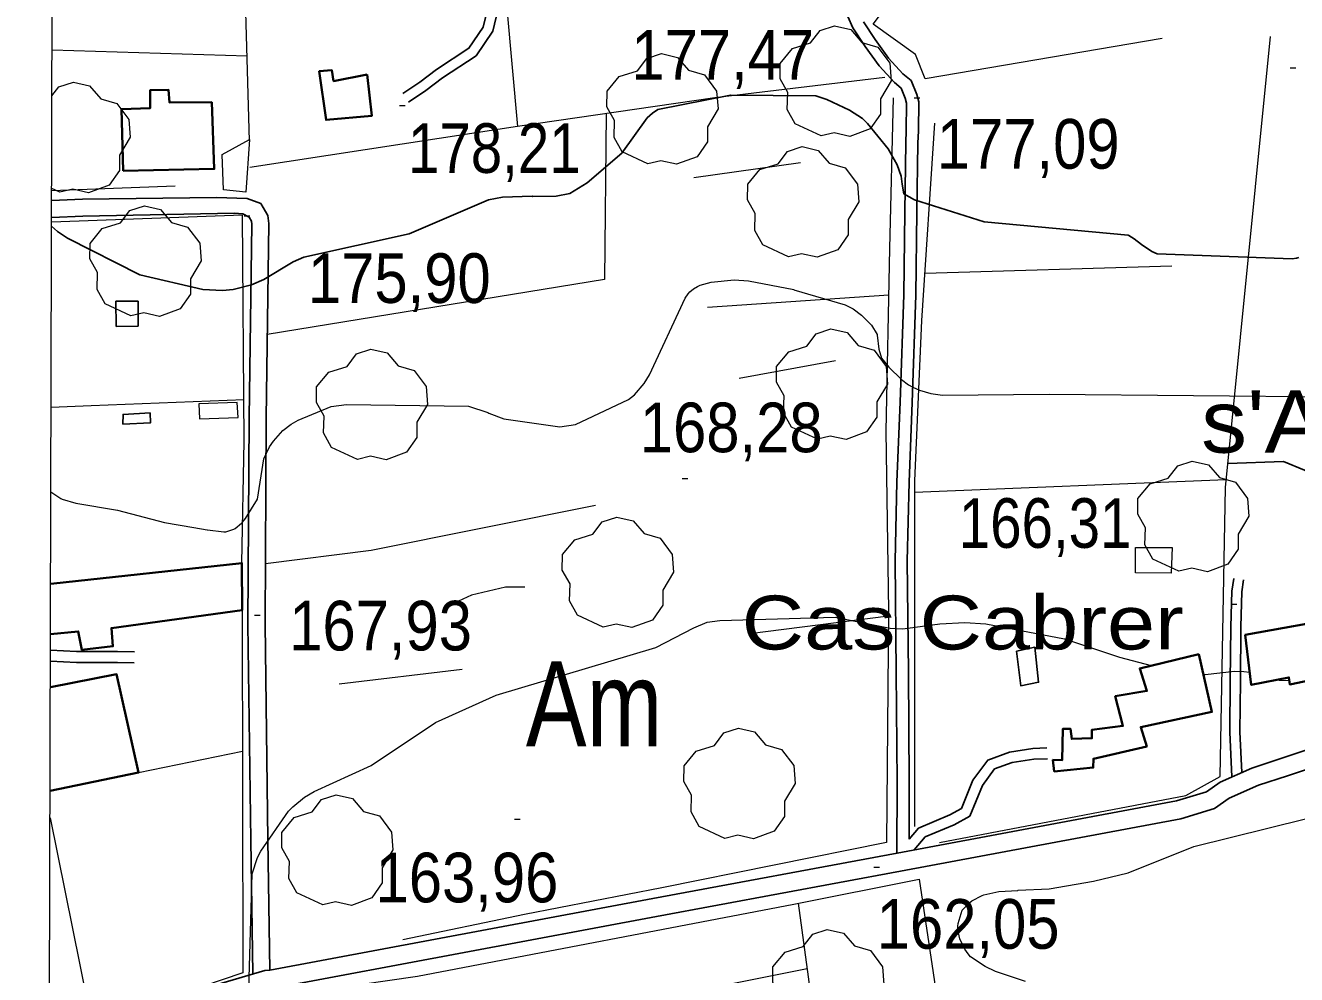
# Model space of a CAD drawing. Extents: x 480269 to 484877, y 4383588 to 4386804.
# Drawn here: x 480523.1 to 480747.1, y 4385794.6 to 4385961.9 of the extents above; entities that cross this region are included whole.
import ezdxf
from ezdxf.enums import TextEntityAlignment as Align

# ---------------------------------------------------------------- set-up
doc = ezdxf.new("R2010")
doc.units = 0
doc.header["$LTSCALE"] = 3.8
doc.linetypes.add('LONG_DASHED', pattern=[7.5, 6, -1.5])
doc.linetypes.add('MEDIUM_DASHED', pattern=[4.5, 3, -1.5])
for name, color, linetype, lineweight in [('1', 7, 'Continuous', 13), ('21', 7, 'Continuous', 25), ('25', 7, 'LONG_DASHED', 25), ('29', 7, 'Continuous', 13), ('36', 7, 'Continuous', 25), ('38', 7, 'Continuous', 25), ('47', 7, 'Continuous', 35), ('48', 7, 'MEDIUM_DASHED', 25), ('51', 7, 'Continuous', 13), ('7', 7, 'Continuous', 13), ('8', 7, 'Continuous', 25), ('9', 7, 'Continuous', 13)]:
    doc.layers.add(name, color=color, linetype=linetype, lineweight=lineweight)
doc.layers.add('31', color=7, linetype='Continuous')
doc.layers.add('5', color=7, linetype='Continuous')

msp = doc.modelspace()

# ---------------------------------------------------------------- linework, layer by layer
at = {"layer": '1'}
msp.add_lwpolyline([(480529.1, 4386456.6), (484105.5, 4386448.1), (484100.5, 4384135.8), (480523.1, 4384144.4)], close=True, dxfattribs=at)
at = {"layer": '21'}
for points in [[(480540.25, 4385891.65), (480545.16, 4385891.9), (480545.07, 4385893.64), (480540.32, 4385893.36)], [(480700.95, 4385852.32), (480701.64, 4385846.17), (480698.49, 4385845.55), (480697.75, 4385851.63)]]:
    msp.add_lwpolyline(points, close=True, dxfattribs=at)
at = {"layer": '25'}
msp.add_lwpolyline([(480767.61, 4385841.45), (480767.42, 4385847.58), (480771.36, 4385854.49), (480775.03, 4385857.97), (480782.21, 4385867), (480780.15, 4385876.58), (480770.59, 4385882.49), (480763.05, 4385883.56), (480753.17, 4385881.59), (480744.81, 4385885.08), (480735, 4385884.7)], dxfattribs=at)
at = {"layer": '29'}
msp.add_line((480529.17, 4385932.52), (480527.74, 4385933.19), dxfattribs=at)
for points in [[(480663.3, 4385942.45), (480658.76, 4385944.57), (480657.35, 4385947.11), (480657.45, 4385950.09), (480656.08, 4385952.5), (480656.12, 4385955.25), (480658.28, 4385957.85), (480661.47, 4385958.85), (480663.12, 4385961.04), (480665.69, 4385961.87), (480668.55, 4385961.22), (480670.5, 4385958.95), (480673.31, 4385958.13), (480675.44, 4385955.28), (480675.68, 4385952.15), (480673.8, 4385949), (480673.8, 4385946.32), (480671.98, 4385943.71), (480668.36, 4385942.37), (480665.59, 4385943)], [(480632.77, 4385937.54), (480628.23, 4385939.66), (480626.82, 4385942.2), (480626.92, 4385945.18), (480625.55, 4385947.59), (480625.59, 4385950.34), (480627.75, 4385952.94), (480630.94, 4385953.94), (480632.59, 4385956.13), (480635.16, 4385956.96), (480638.02, 4385956.31), (480639.97, 4385954.04), (480642.78, 4385953.22), (480644.91, 4385950.37), (480645.15, 4385947.24), (480643.27, 4385944.09), (480643.27, 4385941.41), (480641.45, 4385938.8), (480637.83, 4385937.46), (480635.06, 4385938.09)], [(480657.56, 4385921.15), (480653.02, 4385923.27), (480651.61, 4385925.81), (480651.71, 4385928.79), (480650.34, 4385931.2), (480650.38, 4385933.95), (480652.54, 4385936.55), (480655.73, 4385937.55), (480657.38, 4385939.74), (480659.95, 4385940.57), (480662.81, 4385939.92), (480664.76, 4385937.65), (480667.57, 4385936.83), (480669.7, 4385933.98), (480669.94, 4385930.85), (480668.06, 4385927.7), (480668.06, 4385925.02), (480666.24, 4385922.41), (480662.62, 4385921.07), (480659.85, 4385921.7)], [(480541.67, 4385910.72), (480537.13, 4385912.84), (480535.72, 4385915.38), (480535.82, 4385918.36), (480534.45, 4385920.77), (480534.49, 4385923.52), (480536.65, 4385926.12), (480539.84, 4385927.12), (480541.49, 4385929.31), (480544.06, 4385930.14), (480546.92, 4385929.49), (480548.87, 4385927.22), (480551.68, 4385926.4), (480553.81, 4385923.55), (480554.05, 4385920.42), (480552.17, 4385917.27), (480552.17, 4385914.59), (480550.35, 4385911.98), (480546.73, 4385910.64), (480543.96, 4385911.27)], [(480662.65, 4385889.01), (480658.11, 4385891.13), (480656.7, 4385893.67), (480656.8, 4385896.65), (480655.43, 4385899.06), (480655.47, 4385901.81), (480657.63, 4385904.41), (480660.82, 4385905.41), (480662.47, 4385907.6), (480665.04, 4385908.43), (480667.9, 4385907.78), (480669.85, 4385905.51), (480672.66, 4385904.69), (480674.79, 4385901.84), (480675.03, 4385898.71), (480673.15, 4385895.56), (480673.15, 4385892.88), (480671.33, 4385890.27), (480667.71, 4385888.93), (480664.94, 4385889.56)], [(480581.6, 4385885.44), (480577.06, 4385887.56), (480575.65, 4385890.1), (480575.75, 4385893.08), (480574.38, 4385895.49), (480574.42, 4385898.24), (480576.58, 4385900.84), (480579.77, 4385901.84), (480581.42, 4385904.03), (480583.99, 4385904.86), (480586.85, 4385904.21), (480588.8, 4385901.94), (480591.61, 4385901.12), (480593.74, 4385898.27), (480593.98, 4385895.14), (480592.1, 4385891.99), (480592.1, 4385889.31), (480590.28, 4385886.7), (480586.66, 4385885.36), (480583.89, 4385885.99)], [(480726.33, 4385865.72), (480721.79, 4385867.84), (480720.38, 4385870.38), (480720.48, 4385873.36), (480719.11, 4385875.77), (480719.15, 4385878.52), (480721.31, 4385881.12), (480724.5, 4385882.12), (480726.15, 4385884.31), (480728.72, 4385885.14), (480731.58, 4385884.49), (480733.53, 4385882.22), (480736.34, 4385881.4), (480738.47, 4385878.55), (480738.71, 4385875.42), (480736.83, 4385872.27), (480736.83, 4385869.59), (480735.01, 4385866.98), (480731.39, 4385865.64), (480728.62, 4385866.27)], [(480624.93, 4385855.86), (480620.39, 4385857.98), (480618.98, 4385860.52), (480619.08, 4385863.5), (480617.71, 4385865.91), (480617.75, 4385868.66), (480619.91, 4385871.26), (480623.1, 4385872.26), (480624.75, 4385874.45), (480627.32, 4385875.28), (480630.18, 4385874.63), (480632.13, 4385872.36), (480634.94, 4385871.54), (480637.07, 4385868.69), (480637.31, 4385865.56), (480635.43, 4385862.41), (480635.43, 4385859.73), (480633.61, 4385857.12), (480629.99, 4385855.78), (480627.22, 4385856.41)], [(480646.34, 4385818.63), (480641.8, 4385820.75), (480640.39, 4385823.29), (480640.49, 4385826.27), (480639.12, 4385828.68), (480639.16, 4385831.43), (480641.32, 4385834.03), (480644.51, 4385835.03), (480646.16, 4385837.22), (480648.73, 4385838.05), (480651.59, 4385837.4), (480653.54, 4385835.13), (480656.35, 4385834.31), (480658.48, 4385831.46), (480658.72, 4385828.33), (480656.84, 4385825.18), (480656.84, 4385822.5), (480655.02, 4385819.89), (480651.4, 4385818.55), (480648.63, 4385819.18)], [(480575.48, 4385806.9), (480570.94, 4385809.02), (480569.53, 4385811.56), (480569.63, 4385814.54), (480568.26, 4385816.95), (480568.3, 4385819.7), (480570.46, 4385822.3), (480573.65, 4385823.3), (480575.3, 4385825.49), (480577.87, 4385826.32), (480580.73, 4385825.67), (480582.68, 4385823.4), (480585.49, 4385822.58), (480587.62, 4385819.73), (480587.86, 4385816.6), (480585.98, 4385813.45), (480585.98, 4385810.77), (480584.16, 4385808.16), (480580.54, 4385806.82), (480577.77, 4385807.45)], [(480662.01, 4385783.18), (480657.47, 4385785.3), (480656.06, 4385787.84), (480656.16, 4385790.82), (480654.79, 4385793.23), (480654.83, 4385795.98), (480656.99, 4385798.58), (480660.18, 4385799.58), (480661.83, 4385801.77), (480664.4, 4385802.6), (480667.26, 4385801.95), (480669.21, 4385799.68), (480672.02, 4385798.86), (480674.15, 4385796.01), (480674.39, 4385792.88), (480672.51, 4385789.73), (480672.51, 4385787.05), (480670.69, 4385784.44), (480667.07, 4385783.1), (480664.3, 4385783.73)]]:
    msp.add_lwpolyline(points, close=True, dxfattribs=at)
msp.add_lwpolyline([(480527.78, 4385949.51), (480528.99, 4385951.11), (480531.56, 4385951.94), (480534.42, 4385951.29), (480536.37, 4385949.02), (480539.18, 4385948.2), (480541.31, 4385945.35), (480541.55, 4385942.22), (480539.67, 4385939.07), (480539.67, 4385936.39), (480537.85, 4385933.78), (480534.23, 4385932.44), (480531.46, 4385933.07), (480529.17, 4385932.52)], dxfattribs=at)
at = {"layer": '36'}
for points in [[(480566.54, 4385792.17), (480634.29, 4385804.84), (480677.3, 4385812.85), (480726.72, 4385822.07), (480732.66, 4385823.91), (480735.23, 4385825.7), (480740.41, 4385828.01), (480745.5, 4385829.68), (480759.24, 4385834.23), (480769.59, 4385837.29), (480776.08, 4385840.04), (480778.79, 4385842.18), (480795.64, 4385865.78), (480797.02, 4385869.47), (480798.26, 4385876.17), (480806.98, 4385937.5), (480809.12, 4385941.41), (480811.72, 4385943.55), (480812.85, 4385944.68), (480834.42, 4385956.74), (480848.56, 4385965.34), (480854.48, 4385969.26), (480893.21, 4386011.29)], [(480556.71, 4385792.84), (480565.26, 4385795.35), (480566.15, 4385795.4), (480633.69, 4385808.03), (480676.71, 4385816.04), (480725.94, 4385825.23), (480731.22, 4385826.86), (480733.63, 4385828.54), (480739.24, 4385831.04), (480744.48, 4385832.76), (480758.27, 4385837.33)]]:
    msp.add_lwpolyline(points, dxfattribs=at)
at = {"layer": '38'}
for points in [[(480599.7, 4386021.29), (480600.83, 4386009.18), (480602.77, 4385992.82), (480604.05, 4385980.72), (480604.46, 4385969.74), (480604.85, 4385966.18), (480603.79, 4385961.66), (480601.25, 4385957.91), (480595.55, 4385954.18), (480592.61, 4385951.93), (480589.62, 4385949.91)], [(480676.67, 4385816.03), (480676.69, 4385828.54), (480676.57, 4385847.94), (480676.34, 4385867.55), (480676.68, 4385881.51), (480677.26, 4385895.54), (480677.9, 4385914.45), (480678.06, 4385929.07), (480678.23, 4385941.27), (480678.33, 4385943.42), (480678.37, 4385948.21), (480678.15, 4385949.13), (480677.41, 4385950.9), (480676.23, 4385951.87), (480673.55, 4385954.8), (480671.08, 4385958.22), (480668.93, 4385961.51), (480668.02, 4385963.5)], [(480678.81, 4385818.47), (480678.82, 4385828.54), (480678.7, 4385847.96), (480678.47, 4385867.54), (480678.81, 4385881.44), (480679.39, 4385895.46), (480680.03, 4385914.4), (480680.19, 4385929.05), (480680.36, 4385941.2), (480680.46, 4385943.36), (480680.51, 4385948.44), (480680.19, 4385949.79), (480679.18, 4385952.21), (480677.71, 4385953.42), (480675.21, 4385956.15), (480672.84, 4385959.43), (480670.81, 4385962.55)], [(480566.19, 4385795.41), (480565.84, 4385818.37), (480565.32, 4385856.38), (480565.51, 4385892.72), (480565.97, 4385927.04), (480565.83, 4385928.43), (480564.56, 4385930.56), (480562.2, 4385931.44), (480556.75, 4385931.61), (480533.13, 4385931.3), (480527.74, 4385931.1)], [(480563.2, 4385794.75), (480562.84, 4385818.33), (480562.32, 4385856.37), (480562.51, 4385892.75), (480562.97, 4385926.91), (480562.92, 4385927.46), (480562.53, 4385928.12), (480561.41, 4385928.7), (480559.89, 4385928.87), (480533.2, 4385928.3), (480527.73, 4385928.09)], [(480735.71, 4385829.47), (480735.36, 4385837.36), (480735.42, 4385846.36), (480735.51, 4385855.93), (480735.69, 4385862.23), (480736.02, 4385864.45)], [(480737.45, 4385830.24), (480737.13, 4385837.39), (480737.19, 4385846.35), (480737.28, 4385855.9), (480737.46, 4385862.08), (480737.77, 4385864.19)], [(480527.53, 4385851.83), (480532.13, 4385851.58), (480539.32, 4385851.6), (480542.32, 4385851.53)], [(480678.81, 4385818.47), (480680.49, 4385820.45), (480685.97, 4385822.76), (480688.04, 4385823.89), (480690.06, 4385828.92), (480692.68, 4385832.45), (480696.52, 4385833.86), (480700.63, 4385834.46), (480703.1, 4385834.57)]]:
    msp.add_lwpolyline(points, dxfattribs=at)
at = {"layer": '38', "linetype": 'MEDIUM_DASHED'}
for points in [[(480601.71, 4386019.12), (480602.62, 4386009.37), (480604.56, 4385993.02), (480605.85, 4385980.84), (480606.26, 4385969.87), (480606.68, 4385966.07), (480605.46, 4385960.93), (480602.54, 4385956.6), (480596.59, 4385952.71), (480593.66, 4385950.46), (480590.63, 4385948.42)], [(480527.53, 4385849.89), (480532.08, 4385849.64), (480539.3, 4385849.66), (480542.27, 4385849.59)], [(480679.7, 4385816.6), (480681.65, 4385818.88), (480686.79, 4385821.05), (480689.54, 4385822.54), (480691.73, 4385827.98), (480693.87, 4385830.87), (480696.99, 4385832.01), (480700.81, 4385832.57), (480703.18, 4385832.67)]]:
    msp.add_lwpolyline(points, dxfattribs=at)
at = {"layer": '47'}
for points in [[(480583.33, 4385953.27), (480584.15, 4385946.02), (480576.07, 4385945.29), (480574.89, 4385953.87), (480577.07, 4385954.07), (480577.39, 4385952.14)], [(480540.31, 4385936.31), (480540.05, 4385947.15), (480545.07, 4385947.33), (480545.11, 4385950.53), (480548.34, 4385950.58), (480548.47, 4385948.38), (480555.94, 4385948.41), (480556.37, 4385936.65)], [(480738.06, 4385854.5), (480739.1, 4385845.69), (480745.74, 4385847), (480745.89, 4385845.78), (480758.5, 4385848.42), (480755.7, 4385857.67)], [(480729.86, 4385851.09), (480732.17, 4385840.93), (480719.64, 4385838.25), (480720.7, 4385834.86), (480711.3, 4385832.66), (480711.28, 4385831.1), (480704.4, 4385830.44), (480704.17, 4385832.46), (480705.82, 4385832.44), (480705.94, 4385837.96), (480707.29, 4385837.94), (480707.48, 4385836.17), (480711.03, 4385836.28), (480711.05, 4385837.77), (480716.49, 4385838.47), (480715.14, 4385843.69), (480720.72, 4385844.62), (480719.47, 4385848.6)]]:
    msp.add_lwpolyline(points, close=True, dxfattribs=at)
at = {"layer": '47', "lineweight": 13}
for points in [[(480557.76, 4385939.2), (480562.58, 4385941.82), (480561.95, 4385932.57), (480558.01, 4385932.95)], [(480553.63, 4385895.24), (480553.78, 4385892.58), (480560.59, 4385892.85), (480560.42, 4385895.48)], [(480718.72, 4385865.45), (480718.74, 4385869.91), (480725.15, 4385869.89), (480725, 4385865.38)]]:
    msp.add_lwpolyline(points, close=True, dxfattribs=at)
at = {"layer": '47'}
for points in [[(480527.56, 4385863.53), (480561.25, 4385867.16), (480561.27, 4385858.85), (480538.26, 4385855.71), (480538.53, 4385852.5), (480533.05, 4385851.87), (480532.41, 4385855.13), (480527.54, 4385854.66)], [(480527.51, 4385845.27), (480539.15, 4385847.57), (480543.03, 4385830.24), (480527.47, 4385827.03)]]:
    msp.add_lwpolyline(points, dxfattribs=at)
at = {"layer": '48'}
msp.add_lwpolyline([(480539.07, 4385908.89), (480542.97, 4385908.9), (480542.96, 4385913.32), (480539.06, 4385913.31)], close=True, dxfattribs=at)
at = {"layer": '51'}
for p, q in [((480527.81, 4385957.63), (480562.16, 4385956.55)), ((480640.91, 4385935.12), (480659.66, 4385937.79)), ((480527.74, 4385932.84), (480549.48, 4385933.66)), ((480681.58, 4385918.25), (480725.1, 4385919.55)), ((480675.23, 4385914.39), (480643.31, 4385912.2)), ((480648.89, 4385899.78), (480665.86, 4385902.89)), ((480734.72, 4385881.86), (480679.76, 4385879.58)), ((480675.2, 4385857.81), (480650.77, 4385854.72)), ((480600.07, 4385848.41), (480578.41, 4385845.8)), ((480543.03, 4385830.24), (480561.33, 4385834.01)), ((480527.45, 4385822.26), (480534.78, 4385786.08)), ((480660.86, 4385795.61), (480602.6, 4385784.1))]:
    msp.add_line(p, q, dxfattribs=at)
for points in [[(480562.58, 4385941.61), (480558.8, 4386073.68), (480535.37, 4386089.45), (480528.07, 4386059.14)], [(480628.8, 4386026.5), (480604.96, 4386023.31), (480603.76, 4386022.66), (480602.7, 4386020.93), (480602.22, 4386019.13), (480602.19, 4386018.65), (480605.07, 4385996.83), (480609.82, 4385944.1)], [(480723.44, 4385959.66), (480681.63, 4385952.53), (480679.97, 4385956.83), (480672.51, 4385962.18), (480678.63, 4385970.3), (480688.64, 4385971.97)], [(480684.18, 4385817.9), (480727.58, 4385826.18), (480733.63, 4385829.55), (480734.58, 4385880.48), (480742.5, 4385959.98)], [(480674.53, 4385952.74), (480644.57, 4385949.18), (480609.82, 4385944.1), (480562.63, 4385936.89)], [(480676.04, 4385949.17), (480675.39, 4385922.63), (480674.71, 4385890.39), (480675.2, 4385858.73), (480674.83, 4385817.9), (480635.23, 4385809.93), (480611.05, 4385805.24), (480589.59, 4385800.73)], [(480625.41, 4385946.39), (480625.13, 4385917.16), (480565.71, 4385907.48)], [(480683.28, 4385944.72), (480681.03, 4385909.91), (480679.76, 4385881.66), (480679.79, 4385860.73), (480679.8, 4385820.71)], [(480561.25, 4385867.16), (480561.67, 4385888.66), (480561.34, 4385928.48), (480527.73, 4385927.23)], [(480527.64, 4385894.67), (480534.66, 4385894.93), (480561.62, 4385895.98)], [(480565.38, 4385867.11), (480584.05, 4385869.41), (480623.56, 4385877.39)], [(480611.08, 4385862.89), (480607.71, 4385862.91), (480601.69, 4385861.48), (480599.43, 4385860.44)], [(480561.27, 4385858.85), (480561.43, 4385794.96), (480536.62, 4385786.52), (480527.36, 4385784.28)], [(480527.34, 4385776.59), (480567.42, 4385790.78), (480592.2, 4385794.32), (480658.53, 4385807.06), (480680.6, 4385811.47), (480687.26, 4385767.03), (480690.66, 4385736.36)], [(480659.28, 4385807.21), (480663.92, 4385773.02), (480669.99, 4385728)]]:
    msp.add_lwpolyline(points, dxfattribs=at)
at = {"layer": '7'}
for p, q in [((480745.95, 4385954.45), (480746.95, 4385954.45)), ((480588.99, 4385947.8), (480589.99, 4385947.8)), ((480679.73, 4385949.16), (480680.73, 4385949.16)), ((480561.62, 4385928.35), (480562.62, 4385928.35)), ((480638.82, 4385882.1), (480639.82, 4385882.1)), ((480735.55, 4385859.91), (480736.55, 4385859.91)), ((480563.47, 4385857.98), (480564.47, 4385857.98)), ((480609.29, 4385822.02), (480610.29, 4385822.02)), ((480672.62, 4385813.55), (480673.62, 4385813.55))]:
    msp.add_line(p, q, dxfattribs=at)
at = {"layer": '8'}
msp.add_lwpolyline([(480747.47, 4385921.04), (480747.09, 4385920.92), (480746.3, 4385920.78), (480722.54, 4385921.69), (480721.58, 4385922.07), (480719.78, 4385923.32), (480718.5, 4385924.34), (480717.52, 4385924.92), (480717.41, 4385924.97), (480692.07, 4385927.32), (480679.76, 4385931.22), (480677.9, 4385932.25), (480677.57, 4385933.98), (480677.44, 4385935.37), (480676.7, 4385937.36), (480675.16, 4385940.16), (480671.5, 4385944.66), (480670.63, 4385945.52), (480668.3, 4385947), (480664.31, 4385948.89), (480662.54, 4385949.46), (480662.37, 4385949.5), (480647.32, 4385949.65), (480634.55, 4385947.09), (480633.6, 4385946.48), (480632.67, 4385945.62), (480628.18, 4385939.41), (480622.07, 4385934.2), (480619.05, 4385932.29), (480616.62, 4385931.84), (480616.61, 4385931.83), (480616.6, 4385931.82), (480612.52, 4385931.8), (480612.38, 4385931.83), (480607.17, 4385931.69), (480604.7, 4385931.2), (480590.75, 4385925.2), (480572.17, 4385921.09), (480570.27, 4385920.28), (480565.11, 4385917.16), (480562.94, 4385916.24), (480559.71, 4385915.41), (480557.85, 4385915.23), (480554.34, 4385915.39), (480543.28, 4385917.99), (480530.52, 4385924.42), (480528.78, 4385925.62), (480527.72, 4385926.58)], dxfattribs=at)
at = {"layer": '9'}
for points in [[(480561.86, 4385875.03), (480564, 4385878.44), (480565.13, 4385885.53), (480566.11, 4385887.63), (480566.8, 4385888.66), (480568.47, 4385890.55), (480569.91, 4385891.66), (480571.18, 4385892.37), (480576.97, 4385894.76), (480579.67, 4385895.14), (480601.15, 4385894.84), (480604.57, 4385893.71), (480604.78, 4385893.6), (480607.38, 4385892.58), (480617.25, 4385891.19), (480620.01, 4385891.62), (480629.39, 4385896), (480630.41, 4385896.84), (480632.11, 4385898.8), (480633.08, 4385900.32), (480639.33, 4385913.85), (480639.86, 4385914.63), (480640.19, 4385914.99), (480640.84, 4385915.53), (480641.56, 4385915.94), (480641.99, 4385916.13), (480643.94, 4385916.71), (480647.99, 4385917.1), (480650.51, 4385916.93), (480658.5, 4385915.36), (480658.51, 4385915.35), (480667.55, 4385912.69), (480668.95, 4385911.97), (480670.42, 4385910.87), (480672.2, 4385909.08), (480673.2, 4385907.45), (480673.21, 4385907.41), (480673.21, 4385907.39), (480673.21, 4385907.35), (480673.22, 4385907.32), (480673.46, 4385904.85), (480673.95, 4385903.28), (480675.22, 4385901.7), (480677.48, 4385899.51), (480678.73, 4385898.59), (480679.48, 4385898.18), (480680.67, 4385897.66), (480682.64, 4385897.06), (480684.71, 4385896.75), (480703.53, 4385896.93), (480754.38, 4385896.47)], [(480527.6, 4385879.7), (480529.36, 4385878.52), (480529.57, 4385878.43), (480531.98, 4385877.7), (480539.3, 4385876.48), (480547.6, 4385874.33), (480552.77, 4385873.42), (480552.78, 4385873.42), (480555.11, 4385873.03), (480555.16, 4385873.02), (480558.08, 4385872.69), (480558.42, 4385872.7), (480559.81, 4385873.13), (480560.07, 4385873.27), (480561.15, 4385874.18), (480561.33, 4385874.36), (480561.86, 4385875.03)], [(480562.44, 4385791.99), (480563.08, 4385812.38), (480563.97, 4385815.25), (480564.57, 4385816.39), (480569.45, 4385823.45), (480570.2, 4385824.2), (480572.25, 4385825.88), (480573.96, 4385826.92), (480584, 4385831.47), (480595.35, 4385839.08), (480606.05, 4385843.88), (480634.2, 4385852.31), (480640.88, 4385855.76), (480643.25, 4385856.74), (480645.47, 4385857.05), (480665.81, 4385857.65), (480675.5, 4385855.7), (480677.73, 4385855.58), (480684.23, 4385856.47), (480688.65, 4385856.69), (480692.36, 4385856.46), (480706.23, 4385853.81), (480715.89, 4385850.56), (480721.5, 4385849.09)], [(480730.66, 4385847.55), (480730.99, 4385847.51), (480736.18, 4385848.12), (480737.81, 4385848.06), (480738.8, 4385847.91), (480738.84, 4385847.9)], [(480743.72, 4385846.6), (480744.02, 4385846.52), (480745.8, 4385846.48)], [(480699.36, 4385793.38), (480694.04, 4385795.15), (480692.2, 4385796.04), (480689.63, 4385797.76), (480689.21, 4385798.27), (480688.64, 4385799.08), (480687.74, 4385800.93), (480687.43, 4385802.54), (480687.41, 4385803.18), (480687.47, 4385803.62), (480688.2, 4385806), (480688.33, 4385806.17), (480689.53, 4385807.35), (480689.89, 4385807.61), (480691.7, 4385808.57), (480691.99, 4385808.66), (480694.65, 4385809.25), (480698, 4385809.47), (480698.04, 4385809.49), (480698.06, 4385809.5), (480703.49, 4385809.75), (480703.52, 4385809.76), (480703.53, 4385809.76), (480711.31, 4385811.09), (480711.33, 4385811.09), (480717.44, 4385812.56), (480729, 4385817.2), (480755.3, 4385823.7)]]:
    msp.add_lwpolyline(points, dxfattribs=at)

# ---------------------------------------------------------------- texts
at = {"layer": '31', "width": 0.8}
msp.add_text('Am', height=15, dxfattribs=at).set_placement((480623.32, 4385834.86), align=Align.CENTER)
at = {"layer": '5'}
for s, height, width, p in [("s'Arraval", 11, 1.1, (480792.71, 4385886.63)), ('Cas Cabrer', 9.5, 1.2, (480727.25, 4385851.93))]:
    msp.add_text(s, height=height, dxfattribs=dict(at, width=width)).set_placement(p, align=Align.RIGHT)
at = {"layer": '7'}
for s, width, p in [('177,47', 0.9, (480629.88, 4385952.37)), ('177,09', 0.9, (480683.71, 4385936.69)), ('178,21', 0.85, (480590.52, 4385935.94)), ('175,90', 0.9, (480572.88, 4385913.02)), ('168,28', 0.9, (480631.37, 4385886.7)), ('166,31', 0.85, (480687.58, 4385869.85)), ('167,93', 0.9, (480569.58, 4385851.76)), ('163,96', 0.9, (480584.8, 4385807.36)), ('162,05', 0.9, (480673.12, 4385799.18))]:
    msp.add_text(s, height=8.75, dxfattribs=dict(at, width=width)).set_placement(p)

doc.saveas('drawing.dxf')
